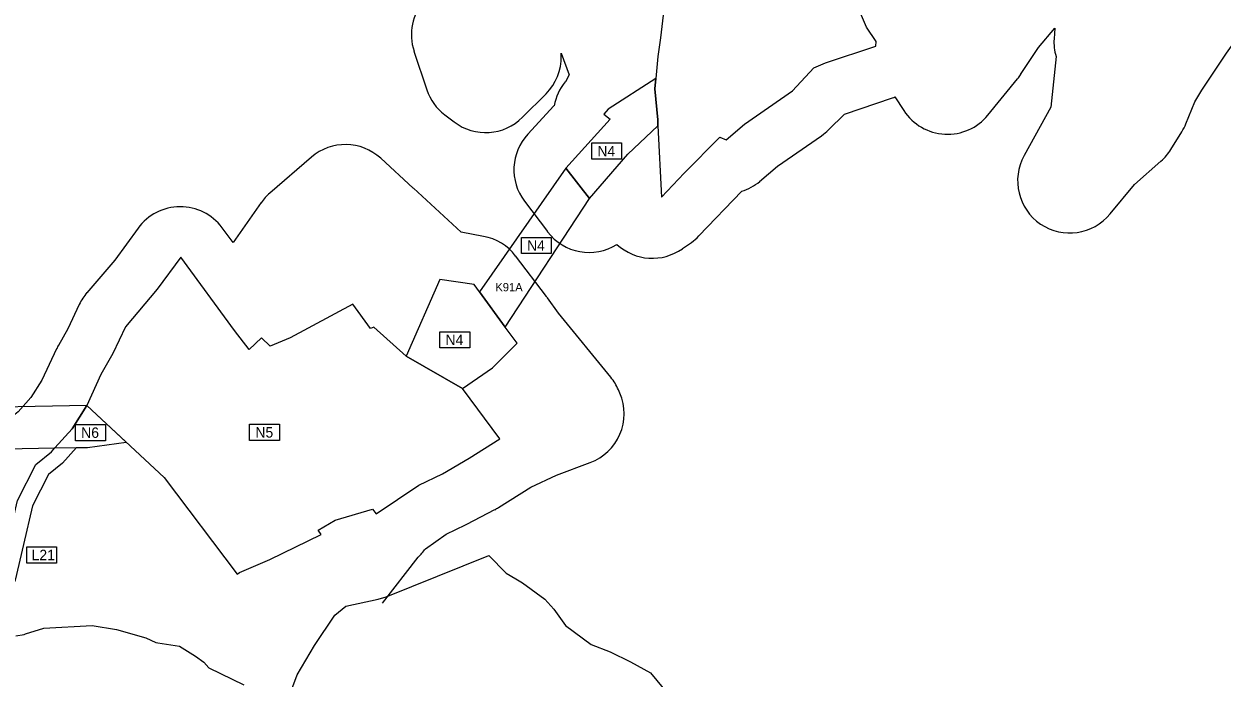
# Model space of a CAD drawing. Extents: x -547623 to -532764, y -1096714 to -1086523.
# Drawn here: x -545785 to -544637, y -1095778 to -1095151 of the extents above; entities that cross this region are included whole.
import ezdxf

# ---------------------------------------------------------------- set-up
doc = ezdxf.new("R2010")
doc.units = 0
for name, color, linetype in [('Vrstva 22', 7, 'Continuous'), ('Vrstva 23', 7, 'Continuous'), ('Vrstva 28', 7, 'Continuous'), ('Vrstva 32', 7, 'Continuous'), ('Vrstva 33', 7, 'Continuous'), ('Vrstva 36', 7, 'Continuous')]:
    doc.layers.add(name, color=color, linetype=linetype)

msp = doc.modelspace()

# ---------------------------------------------------------------- linework, layer by layer
at = {"layer": 'Vrstva 22'}
for points in [[(-545531.8, -1095797.3), (-545523.3, -1095775.1), (-545506.6, -1095746.8), (-545487.2, -1095717.6), (-545476.6, -1095709.1), (-545445.7, -1095702.5), (-545438.2, -1095700.3), (-545339.6, -1095660.7), (-545322.9, -1095677.5), (-545313.8, -1095682.8), (-545307.3, -1095686.6), (-545286, -1095702.5), (-545277.5, -1095712.1), (-545266.2, -1095727.6), (-545241.5, -1095746), (-545223.2, -1095753), (-545203.9, -1095762.5), (-545184.6, -1095773.1), (-545157.4, -1095805.8)], [(-545793, -1095737.5), (-545784.9, -1095736.4), (-545783.9, -1095735.8), (-545766.2, -1095730.2), (-545719.7, -1095727.8), (-545696.6, -1095731.5), (-545668.3, -1095739.6), (-545658.7, -1095744.1), (-545656.9, -1095744.4), (-545636, -1095747.4), (-545620.8, -1095757.2), (-545612.7, -1095762.9), (-545608, -1095768.4), (-545574.5, -1095784.4)]]:
    msp.add_lwpolyline(points, dxfattribs=at)
at = {"layer": 'Vrstva 23'}
for p, q in [((-545411.4, -1095177.2), (-545399.1, -1095214.1)), ((-545270.2, -1095181.7), (-545270.2, -1095178.9)), ((-544861.3, -1095238.4), (-544832.9, -1095203.7)), ((-545307.3, -1095240.5), (-545284.8, -1095217.9)), ((-545277.2, -1095229.5), (-545302.3, -1095256.7)), ((-544950.5, -1095220.9), (-544941.8, -1095234.1)), ((-545381.9, -1095238.1), (-545373, -1095244.9)), ((-544685.9, -1095271.3), (-544675.4, -1095254.3)), ((-545509.7, -1095278.7), (-545549.6, -1095313.1)), ((-545412.1, -1095308.4), (-545443.2, -1095279.8)), ((-545557.9, -1095322.3), (-545584.7, -1095360.6)), ((-545305.5, -1095320.8), (-545283.4, -1095350.1)), ((-545138.4, -1095354.2), (-545097.2, -1095311.4)), ((-545584.7, -1095360.6), (-545595.4, -1095346.3)), ((-545154, -1095366.4), (-545145.5, -1095360.4)), ((-545284.4, -1095412.3), (-545314, -1095373.4)), ((-545214.1, -1095505), (-545215.5, -1095501.7)), ((-545360.8, -1095630.6), (-545334, -1095616.6)), ((-545441.6, -1095706.1), (-545407.5, -1095662.1))]:
    msp.add_line(p, q, dxfattribs=at)
for points in [[(-544829.9, -1095199.6), (-544812.8, -1095173.6), (-544797.3, -1095155.1), (-544797.9, -1095165.2)], [(-544671.5, -1095246.6), (-544663, -1095225.6), (-544656.1, -1095214.5), (-544632.5, -1095179), (-544616.6, -1095156.5), (-544606.9, -1095159.2), (-544597.9, -1095164.1), (-544571.6, -1095183.1)], [(-545270.2, -1095178.9), (-545262.8, -1095199.8), (-545266.2, -1095206.4), (-545266.4, -1095206.6)], [(-544796, -1095182), (-544796, -1095182.1), (-544800.9, -1095230.9), (-544826.5, -1095277.2)], [(-545014, -1095252.5), (-544998.9, -1095237.4), (-544952.7, -1095221.7)], [(-545080.1, -1095301.9), (-545062.9, -1095287.3), (-545020.8, -1095258.1)], [(-544744.1, -1095333.1), (-544720.9, -1095304.9), (-544695.4, -1095282.5)], [(-545344.9, -1095354.6), (-545366.1, -1095350.7), (-545412, -1095308.4)], [(-545675.9, -1095346.8), (-545698, -1095377.3), (-545724.9, -1095408.6)], [(-545222.7, -1095489.7), (-545272.9, -1095428.2), (-545283.5, -1095413.4)], [(-545732.2, -1095419.9), (-545743.2, -1095443.3), (-545752.2, -1095459.1)], [(-545753.9, -1095462.4), (-545768.1, -1095492.4), (-545778.6, -1095509), (-545790.8, -1095522.7), (-545805.2, -1095534.4)], [(-545330.4, -1095614.5), (-545299.5, -1095595), (-545274.7, -1095583.5), (-545242.5, -1095571.5)], [(-545400.3, -1095654.1), (-545380.4, -1095640.1), (-545362.1, -1095631.2)]]:
    msp.add_lwpolyline(points, dxfattribs=at)
for centre, start, end in [((-545363.9, -1095161.4), 138.3665, 198.3511), ((-544748, -1095168.1), 176.7705, 196.2182), ((-545320.2, -1095182.5), 315.0507, 0.9557), ((-545228, -1095238.6), 140.1944, 169.4626), ((-544871.6, -1095172), 320.7151, 326.6102), ((-545351.7, -1095198.3), 198.3511, 232.7327), ((-544968.8, -1095174.4), 288.7653, 291.5194), ((-545342.7, -1095205.1), 232.7327, 315.0507), ((-544900, -1095206.7), 213.2331, 320.7151), ((-545049.3, -1095217), 304.7087, 314.9016), ((-544717.9, -1095228), 328.1709, 338.1005), ((-545265.6, -1095290.7), 137.2342, 217.0382), ((-545477.1, -1095316.6), 47.384, 130.8102), ((-544728.4, -1095244.9), 311.2441, 328.1709), ((-544782.8, -1095301.4), 151.0564, 320.6243), ((-545445.9, -1095345.2), 47.3468, 47.384), ((-545112.4, -1095263.8), 287.7465, 310.3453), ((-545516.9, -1095351), 130.8102, 145.002), ((-545635.4, -1095376.2), 36.7487, 143.9907), ((-545353.7, -1095403.8), 37.3417, 79.7685), ((-545243.5, -1095320), 217.0382, 302.1832), ((-545174.4, -1095319.6), 305.2944, 316.1293), ((-545182.9, -1095325.6), 227.2523, 305.2944), ((-545686.9, -1095441.1), 139.3671, 154.8898), ((-545324.1, -1095442.6), 35.72, 37.3417), ((-545708.7, -1095483.8), 150.3646, 154.5869), ((-545261.5, -1095521.3), 23.1196, 39.1938), ((-545260, -1095524.7), 290.5094, 23.1196), ((-545357.1, -1095572.3), 297.5243, 302.3122), ((-545383.9, -1095586.2), 295.8087, 297.5243), ((-545441.2, -1095625.2), 312.3885, 324.7142)]:
    msp.add_arc(centre, 50, start, end, dxfattribs=at)
at = {"layer": 'Vrstva 28'}
for points in [[(-545265.9, -1095289.1), (-545243.2, -1095318.4), (-545206.5, -1095275.9), (-545177.7, -1095248.6), (-545177.8, -1095242.9), (-545180.4, -1095213.2), (-545179.7, -1095203.4), (-545225.3, -1095232.6), (-545229.3, -1095237.4), (-545223.5, -1095242.4), (-545265.9, -1095289.1)], [(-545348.7, -1095407.7), (-545324, -1095441.7), (-545243.2, -1095318.4), (-545265.9, -1095289.1), (-545348.7, -1095407.7)], [(-545324, -1095441.7), (-545348.7, -1095407.7), (-545353.6, -1095400.9), (-545386.7, -1095396), (-545418.8, -1095469.4), (-545364.9, -1095500.4), (-545336.2, -1095480.7), (-545312.4, -1095457), (-545324, -1095441.7)], [(-545725, -1095516.9), (-545857.1, -1095519.2), (-545941.5, -1095508), (-545958.5, -1095545.7), (-545958.7, -1095546.1), (-545859.4, -1095559.2), (-545842.8, -1095558.9), (-545834.7, -1095558.8), (-545755.5, -1095557.4), (-545738.9, -1095539.2), (-545725, -1095516.9)], [(-545734.9, -1095557.1), (-545724.3, -1095556.9), (-545687.2, -1095552), (-545725, -1095516.9), (-545738.9, -1095539.2), (-545755.5, -1095557.4), (-545734.9, -1095557.1)]]:
    msp.add_lwpolyline(points, dxfattribs=at)
at = {"layer": 'Vrstva 32'}
for points in [[(-545171.2, -1095131.7), (-545175.2, -1095164.2), (-545177.8, -1095182.3), (-545179.7, -1095203.4), (-545180.4, -1095213.2), (-545177.8, -1095242.9), (-545177.7, -1095248.6), (-545174.3, -1095317.1), (-545152.4, -1095294.1), (-545118.3, -1095259.6), (-545112.3, -1095262.2), (-545094.5, -1095247.2), (-545048.7, -1095215), (-545028.2, -1095193.2), (-545016.9, -1095188.3)], [(-545016.9, -1095188.3), (-544968.8, -1095172.4), (-544968.4, -1095167.9), (-544977.6, -1095154), (-544987.5, -1095131.1)], [(-545569.5, -1095463.1), (-545583.4, -1095444.8), (-545635, -1095374.7), (-545657.5, -1095405.2), (-545687.8, -1095441.4), (-545700, -1095466.8), (-545711.6, -1095487), (-545725, -1095516.9)], [(-545329.2, -1095548.8), (-545364.9, -1095500.4), (-545418.8, -1095469.4), (-545449.8, -1095441.6), (-545453, -1095443), (-545470.1, -1095419.5), (-545530, -1095451.9), (-545549.3, -1095459.9), (-545557.6, -1095451.8), (-545569.5, -1095463.1)], [(-545725, -1095516.9), (-545650.8, -1095585.9), (-545580.8, -1095678.4), (-545578.7, -1095676.9), (-545549.5, -1095664.4), (-545500.2, -1095640.5), (-545503.2, -1095636.4), (-545487, -1095626.7), (-545451, -1095616.1)], [(-545451, -1095616.1), (-545447.6, -1095620.6), (-545406.9, -1095593), (-545384.2, -1095582.2), (-545358.6, -1095567.2), (-545329.2, -1095548.8)]]:
    msp.add_lwpolyline(points, dxfattribs=at)
at = {"layer": 'Vrstva 33'}
msp.add_lwpolyline([(-545825, -1095772.2), (-545828.7, -1095754.2), (-545826.2, -1095726.9), (-545823.9, -1095717), (-545822, -1095709.3), (-545808, -1095679.3), (-545800.4, -1095646.7), (-545791.4, -1095607.8), (-545773.8, -1095573.2), (-545758.8, -1095561.1), (-545755.5, -1095557.4), (-545734.9, -1095557.1), (-545748.4, -1095572), (-545761.8, -1095582.9), (-545777.2, -1095613), (-545785.8, -1095650.1), (-545793.8, -1095684.2), (-545807.8, -1095714.2), (-545809.3, -1095720.5), (-545811.4, -1095729.3), (-545813.6, -1095753.4), (-545810.3, -1095769.2), (-545813.2, -1095776.9), (-545825, -1095772.2)], dxfattribs=at)
at = {"layer": 'Vrstva 36'}
for points in [[(-545241, -1095265.1), (-545212.4, -1095265.1), (-545212.4, -1095280.6), (-545241, -1095280.6)], [(-545308.4, -1095355.6), (-545279.8, -1095355.6), (-545279.8, -1095371.1), (-545308.4, -1095371.1)], [(-545386.6, -1095446.1), (-545358, -1095446.1), (-545358, -1095461.6), (-545386.6, -1095461.6)], [(-545735.7, -1095535.1), (-545707.1, -1095535.1), (-545707.1, -1095550.6), (-545735.7, -1095550.6)], [(-545569, -1095534.8), (-545540.4, -1095534.8), (-545540.4, -1095550.2), (-545569, -1095550.2)], [(-545782.6, -1095652.4), (-545754, -1095652.4), (-545754, -1095667.8), (-545782.6, -1095667.8)]]:
    msp.add_lwpolyline(points, close=True, dxfattribs=at)

# ---------------------------------------------------------------- texts
for s, height, p in [('N4', 10, (-545235.6, -1095277.9)), ('N4', 10, (-545303, -1095368.4)), ('K91A', 8, (-545333.4, -1095407.3)), ('N4', 10, (-545381.2, -1095458.8)), ('N6', 10, (-545730.4, -1095547.8)), ('N5', 10, (-545563.4, -1095547.5)), ('L21', 10, (-545777.9, -1095665.1))]:
    msp.add_text(s, height=height, dxfattribs=at).set_placement(p)

doc.saveas('drawing.dxf')
